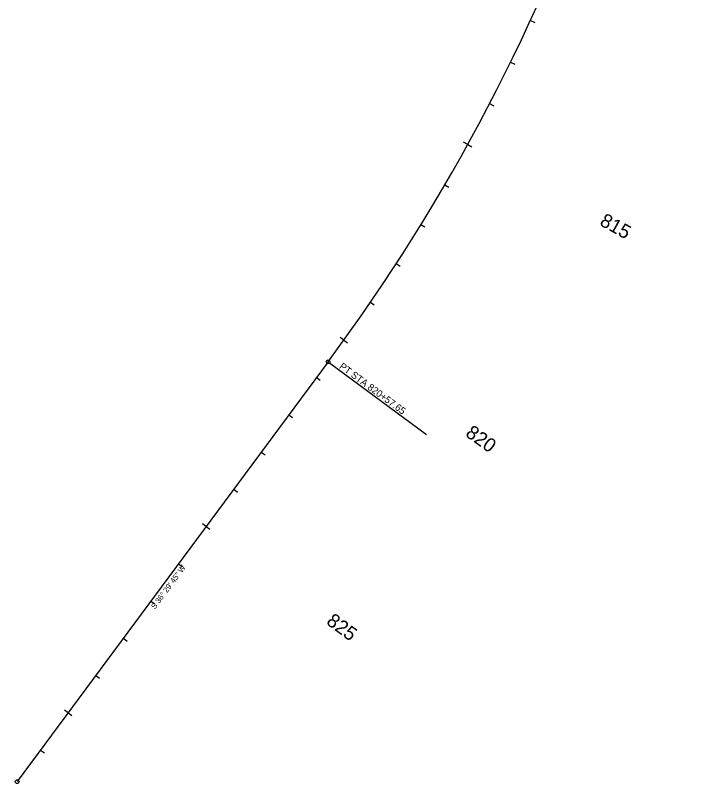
# Model space of a CAD drawing. Extents: x 2819977 to 2827606, y 116785 to 150320.
# Drawn here: x 2822204 to 2823701, y 136089 to 137743 of the extents above; entities that cross this region are included whole.
import ezdxf

# ---------------------------------------------------------------- set-up
doc = ezdxf.new("R2010")
doc.units = 0
for name, color, linetype in [('Default', 7, 'Continuous'), ('Modeling-Contours-Minor-Existing', 7, 'Continuous'), ('Modeling-Flow Arrows-Existing', 7, 'Continuous'), ('Modeling-Spot-Existing', 7, 'Continuous')]:
    doc.layers.add(name, color=color, linetype=linetype)

msp = doc.modelspace()

# ---------------------------------------------------------------- linework, layer by layer
at = {"layer": 'Default'}
msp.add_line((2822878.3, 136994.9), (2822207.8, 136088.7), dxfattribs=at)
msp.add_arc((2819501.9, 139492.9), 4200, 323.5041, 358.849, dxfattribs=at)
at = {"layer": 'Modeling-Flow Arrows-Existing'}
for p, q in [((2823314.7, 137731.5), (2823323.8, 137727.3)), ((2823271.7, 137641.2), (2823280.6, 137636.8)), ((2823226.5, 137552), (2823235.4, 137547.4)), ((2823179.3, 137463.9), (2823170.5, 137468.7)), ((2823179.3, 137463.9), (2823188, 137459)), ((2823129.9, 137376.9), (2823138.5, 137371.9)), ((2823078.5, 137291.1), (2823087, 137285.9)), ((2823025.1, 137206.6), (2823033.5, 137201.1)), ((2822969.6, 137123.4), (2822977.9, 137117.7)), ((2822912.2, 137041.5), (2822904.1, 137047.3)), ((2822912.2, 137041.5), (2822920.4, 137035.6)), ((2822878.3, 136994.9), (2822207.8, 136088.7)), ((2822853.1, 136960.9), (2822861.1, 136954.9)), ((2822793.6, 136880.5), (2822801.6, 136874.5)), ((2822734.1, 136800.1), (2822742.2, 136794.1)), ((2822674.7, 136719.7), (2822682.7, 136713.7)), ((2822615.2, 136639.3), (2822607.1, 136645.2)), ((2822615.2, 136639.3), (2822623.2, 136633.3)), ((2822555.7, 136558.9), (2822563.7, 136553)), ((2822496.2, 136478.5), (2822504.3, 136472.6)), ((2822436.8, 136398.1), (2822444.8, 136392.2)), ((2822377.3, 136317.7), (2822385.3, 136311.8)), ((2822317.8, 136237.3), (2822309.8, 136243.3)), ((2822317.8, 136237.3), (2822325.8, 136231.4)), ((2822258.3, 136157), (2822266.4, 136151))]:
    msp.add_line(p, q, dxfattribs=at)
msp.add_arc((2819501.9, 139492.9), 4200, 323.5041, 358.849, dxfattribs=at)
at = {"layer": 'Modeling-Spot-Existing'}
msp.add_line((2822881.5, 136992.5), (2823090.3, 136838), dxfattribs=at)
for centre in [(2822878.3, 136994.9), (2822207.8, 136088.7)]:
    msp.add_circle(centre, 4, dxfattribs=at)

# ---------------------------------------------------------------- texts
at = {"layer": 'Modeling-Contours-Minor-Existing'}
msp.add_text('S 36%%d 29\' 45" W', height=12, rotation=53.5041, dxfattribs=at).set_placement((2822505, 136460.1))
at = {"layer": 'Modeling-Flow Arrows-Existing'}
for s, rotation, p in [(' 815', 331.1114, (2823452.2, 137296.1)), (' 820', 324.2905, (2823163.3, 136842.5)), (' 825', 323.5041, (2822863.5, 136436.9))]:
    msp.add_text(s, height=30, rotation=rotation, dxfattribs=at).set_placement(p)
at = {"layer": 'Modeling-Spot-Existing'}
msp.add_text('PT STA 820+57.65', height=15, rotation=323.5041, dxfattribs=at).set_placement((2822901, 136981.9))

doc.saveas('drawing.dxf')
